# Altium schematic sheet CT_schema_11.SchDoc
size 391 x 238 mm
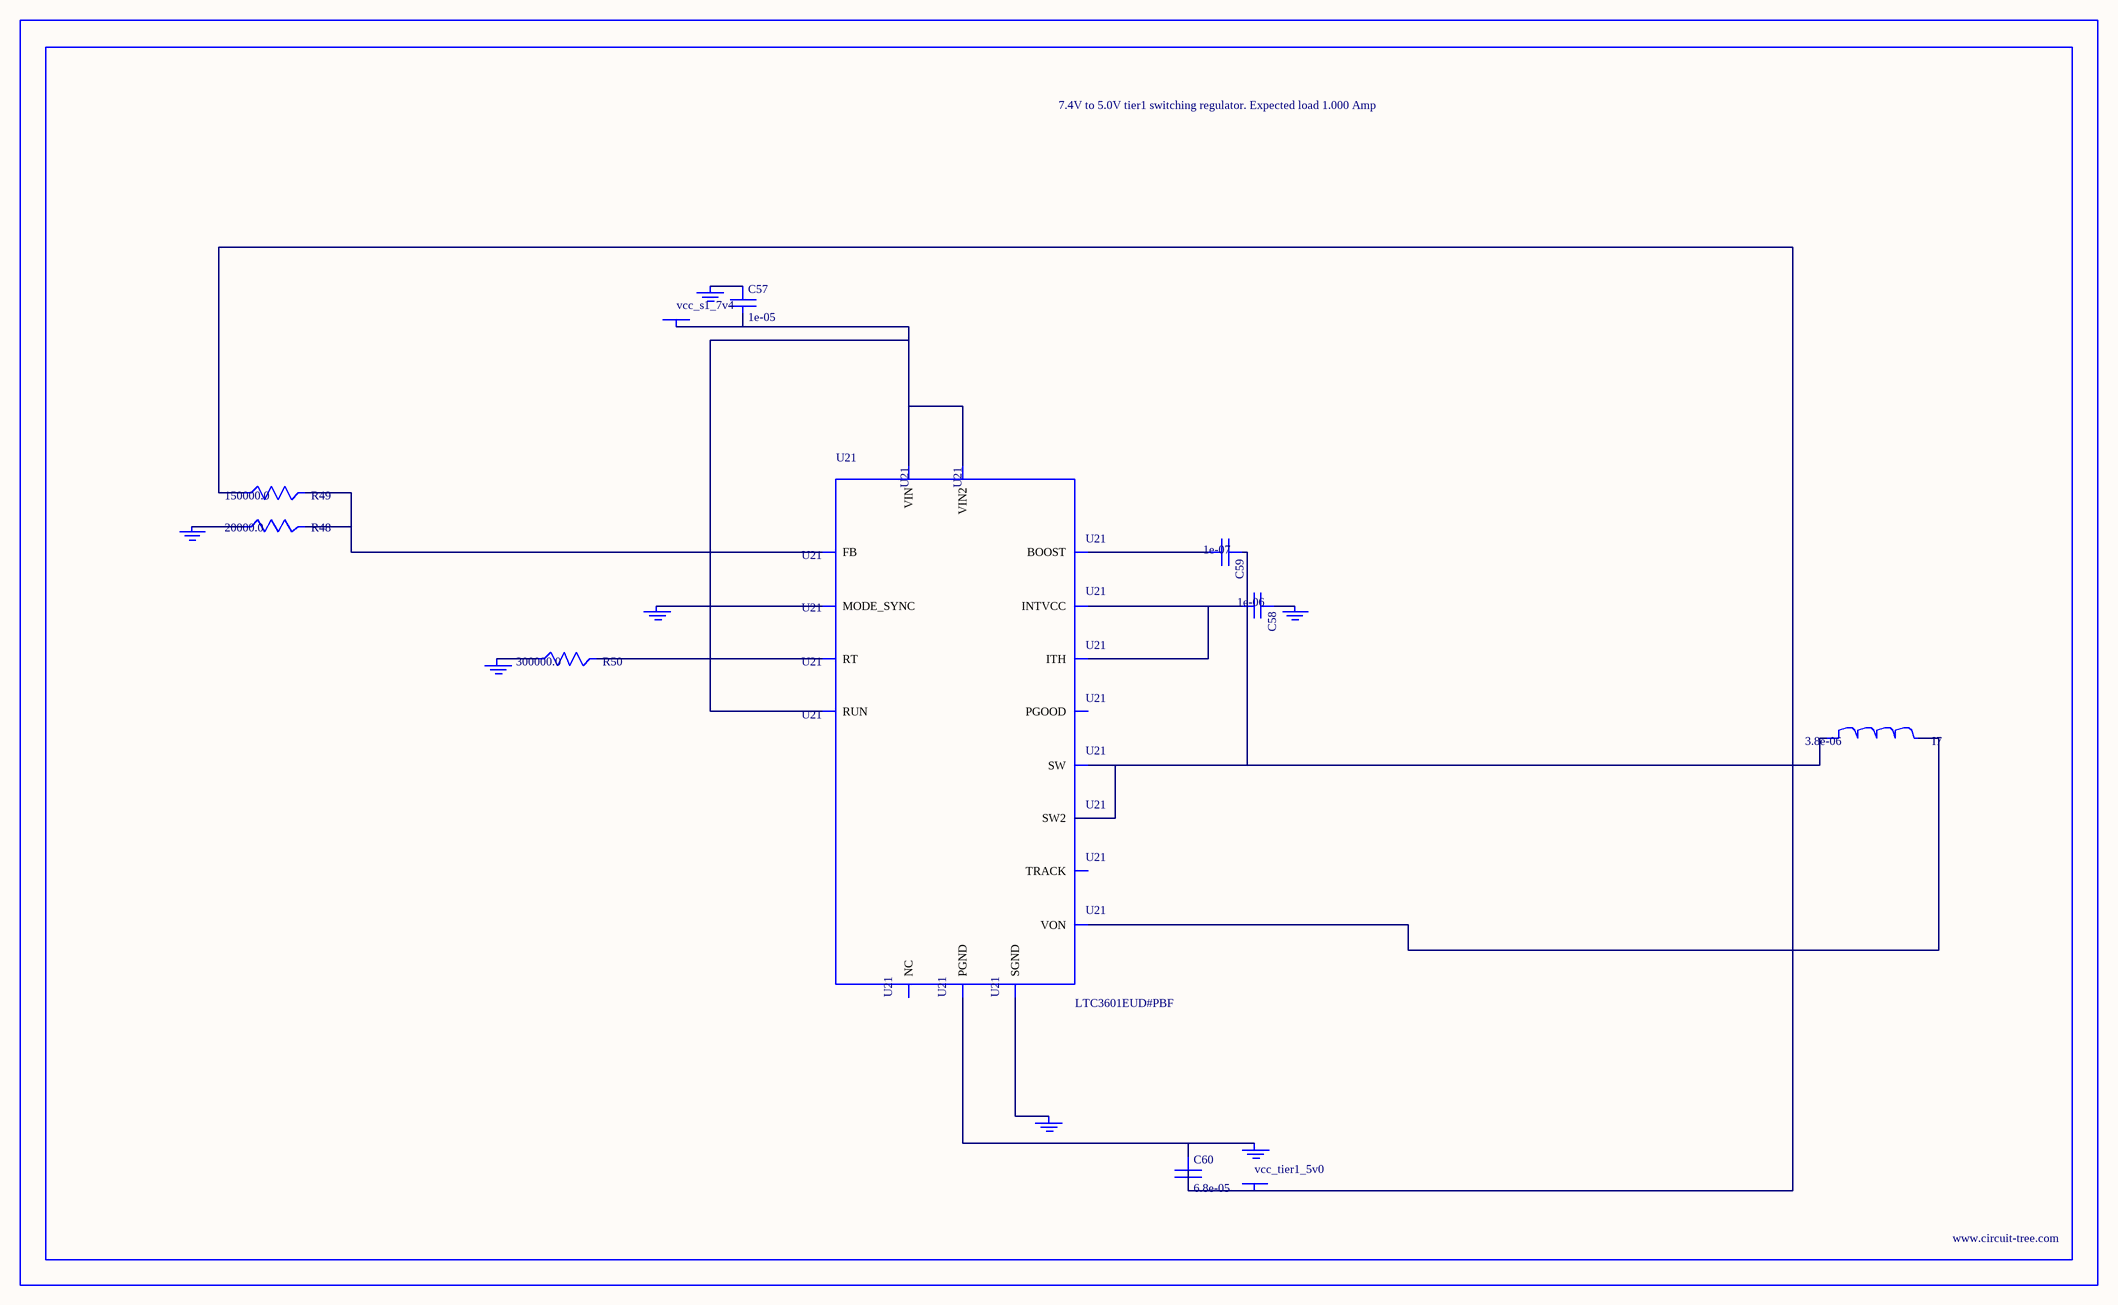
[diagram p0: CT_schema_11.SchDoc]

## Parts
BORDER10  (no value)
C57  1e-05  [C0805]
C58  1e-06  [C0603]
C59  1e-07  [C0402]
C60  6.8e-05  [2220]
GND_INSTANCE_10_0  (no value)
GND_INSTANCE_10_1  (no value)
GND_INSTANCE_10_2  (no value)
GND_INSTANCE_10_3  (no value)
GND_INSTANCE_10_4  (no value)
GND_INSTANCE_10_5  (no value)
GND_INSTANCE_10_6  (no value)
I7  3.8e-06  [DR1040]
POWER_INSTANCE_10_0  vcc_s1_7v4
POWER_INSTANCE_10_1  vcc_tier1_5v0
R48  20000.0  [R0603]
R49  150000.0  [R0603]
R50  300000.0  [R0603]
U21  LTC3601EUD#PBF  [QFN-16_EP]

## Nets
NetC57_1: C57.1 GND_INSTANCE_10_5.0(GND)
NetC57_2: C57.2 POWER_INSTANCE_10_0.0(PWR) U21.14(RUN) U21.15(VIN) U21.16(VIN2)
NetC58_1: C58.1 GND_INSTANCE_10_1.0(GND)
NetC58_2: C58.2 U21.7(INTVCC) U21.12(ITH)
NetC59_1: C59.1 I7.1 U21.3(SW) U21.4(SW2)
NetC59_2: C59.2 U21.6(BOOST)
NetC60_1: C60.1 GND_INSTANCE_10_6.0(GND) U21.17(PGND)
NetC60_2: C60.2 I7.2 POWER_INSTANCE_10_1.0(PWR) R49.1 U21.8(VON)
NetGND_INSTANCE_10_0_0: GND_INSTANCE_10_0.0(GND) U21.1(MODE_SYNC)
NetGND_INSTANCE_10_2_0: GND_INSTANCE_10_2.0(GND) U21.9(SGND)
NetGND_INSTANCE_10_3_0: GND_INSTANCE_10_3.0(GND) R50.1
NetGND_INSTANCE_10_4_0: GND_INSTANCE_10_4.0(GND) R48.1
NetR48_2: R48.2 R49.2 U21.11(FB)
NetR50_2: R50.2 U21.10(RT)

Not connected (* = marked no-connect by the designer): U21 2(PGOOD) 5(NC) 13(TRACK)

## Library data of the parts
BORDER10 = BORDER_PAGE10
C57 = C0805C106K8RACTU
C58 = C0603C105K3RACTU
C59 = C0402C104K3RACTU
C60 = C5750X5R1A686M
GND_INSTANCE_10_0-GND_INSTANCE_10_6 = GND
I7 = DR1040-3R8-R
POWER_INSTANCE_10_0 POWER_INSTANCE_10_1 = PWR
R48 = RC0603JR-0720KL
R49 = RC0603JR-07150KL
R50 = RC0603JR-07300KL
